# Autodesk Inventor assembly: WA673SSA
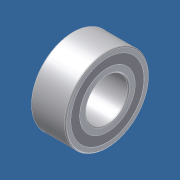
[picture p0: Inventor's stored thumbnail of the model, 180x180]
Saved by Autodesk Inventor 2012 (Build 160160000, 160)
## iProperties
Category: PARTsolutions
Created: 2011-07
Part Number: WA673SSA
Catalog Web Link: www.cadenas.de
Description: With double shield ZZ -
Document SubType Name: Assembly
Designer: PARTsolutions
NB: WA673SSA
NN: With double shield ZZ
NBSYN: $ORDER.
LINA: WA673SSA
PSOL_MULTISOLIDPART: 0.0
SD: 3.0
D: 6
B: 2.0
B1: 2.5
D1: 7.2
D2: 7.2
C1: 0.6
C2: 0.6
R: 0.08
ORDER: WA673SSA
CR: 242
COR: 94
CRF: 25
CORF: 9,5
LSG: 60 000
LSO: 71 000
MASS: 0.20
ORDER1: 673
WSS: WA673SSA
WDS: SSA
UTWF: FL673
FORSS: FLWA673SA
FORDS: SSA
DA1: 3,6
DA2: 4,1
DA: 5,4
RAS: 0,08
MASS1: 0.26
VERS: 3
X: 1.500
N: 9
O: 14.130
RB: 0.444
PPATH: mss_asmtpl.prj
KT: DUMMY
CreationOption_UseAsmMates: 0
SUPPLIER: NTN
ARTICLENO: WA673SSA
BOMINFO: WA673SSA
CREATOR: CADENAS GmbH
PSOL_IDENT_0: {\\10.0.0.251\ps_data\23d-libs\ntn\ball_roller_bearings\miniature_extra_small_bb\metric_system_sizes
PSOL_IDENT_1: \mss_zz_asmtab.prj},181 {VTYP=3D},{STYP=ASSTAB},{NB=WA673SSA},{LINA=WA673SSA},{NN=With double shield
PSOL_IDENT_2: ZZ},{DATE=11.12.2007 08:48:24},{GEOMDATE=17.04.2007},{VERSION=},{LINEID=12590},{LINESUBID=-1},{WBVA
PSOL_IDENT_3: R=}  {NB=WA673SSA},{LINA=WA673SSA},{KT=DUMMY},{IDNR=},{SD=3.0},{D=6},{B=2.0},{B1=2.5},{D1=7.2},{D2=7
PSOL_IDENT_4: .2},{C1=0.6},{C2=0.6},{R=0.08},{ORDER=WA673SSA},{CR=242},{COR=94},{CRF=25},{CORF=9,5},{LSG=60 000},{
PSOL_IDENT_5: LSO=71 000},{MASS=0.20},{ORDER1=673},{WSS=WA673SSA},{WDS=SSA},{UTWF=FL673},{FORSS=FLWA673SA},{FORDS=
PSOL_IDENT_6: SSA},{DA1=3,6},{DA2=4,1},{DA=5,4},{RAS=0,08},{MASS1=0.26},{VERS=3},{X=1.5},{N=9},{O=14.13},{RB=0.444
PSOL_IDENT_7: },{PPATH=mss_asmtpl.prj}
Title: WA673SSA
Author: Cadenas PARTsolutions
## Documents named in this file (5)
- D:\Formulaire\Sujet CIM 2012\Modélisation_7970_shimano\éléments standards\PARTserver35515621\WA673SSA.iam
- D:\Formulaire\Sujet CIM 2012\Modélisation_7970_shimano\éléments standards\PARTserver35515621\WA673SSA_Inner_ring.ipt
- D:\Formulaire\Sujet CIM 2012\Modélisation_7970_shimano\éléments standards\PARTserver35515621\WA673SSA_Outer_ring.ipt
- D:\Formulaire\Sujet CIM 2012\Modélisation_7970_shimano\éléments standards\PARTserver35515621\WA673SSA_Shield.ipt
- D:\Formulaire\Sujet CIM 2012\Modélisation_7970_shimano\éléments standards\PARTserver35515621\WA673SSA_Ball.ipt
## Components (13 placed, 4 different names)
1. WA673SSA Inner ring:1
2. WA673SSA Outer ring:1
3. WA673SSA Shield:1
4. WA673SSA Shield:2
5. WA673SSA Ball:1
6. WA673SSA Ball:2
7. WA673SSA Ball:3
8. WA673SSA Ball:4
9. WA673SSA Ball:5
10. WA673SSA Ball:6
11. WA673SSA Ball:7
12. WA673SSA Ball:8
13. WA673SSA Ball:9
